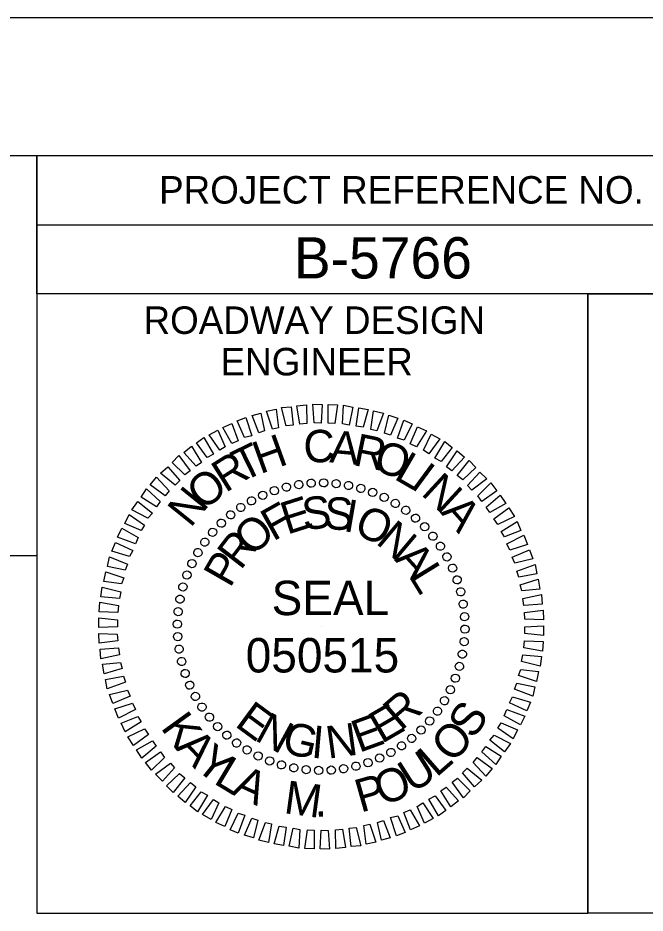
# Model space of a CAD drawing. Extents: x 573078 to 573143.6, y -55221.3 to -55199.3.
# Drawn here: x 573107.444 to 573109.723, y -55202.55 to -55199.298 of the extents above; entities that cross this region are included whole.
import ezdxf

# ---------------------------------------------------------------- set-up
doc = ezdxf.new("R2010")
doc.units = 0
for name, color, linetype in [('Prop Dimension', 7, 'Continuous'), ('Prop DSN Text', 7, 'Continuous'), ('Scratch_Level_1', 7, 'Continuous'), ('Sheet Plan CELL', 7, 'Continuous'), ('Sheet Plot Border Inside CELL', 7, 'Continuous')]:
    doc.layers.add(name, color=color, linetype=linetype)

msp = doc.modelspace()

# ---------------------------------------------------------------- linework, layer by layer
at = {"layer": 'Prop Dimension'}
for p, q in [((573108.4648, -55200.9939), (573108.4648, -55200.9939)), ((573108.5094, -55200.9876), (573108.5094, -55200.9876)), ((573108.5553, -55200.9867), (573108.5553, -55200.9867)), ((573108.6011, -55200.9897), (573108.6011, -55200.9897)), ((573108.646, -55200.9971), (573108.646, -55200.9971)), ((573108.3336, -55201.0314), (573108.3336, -55201.0314)), ((573108.3752, -55201.0147), (573108.3752, -55201.0147)), ((573108.419, -55201.0022), (573108.419, -55201.0022)), ((573108.6897, -55201.0064), (573108.6897, -55201.0064)), ((573108.7335, -55201.0209), (573108.7335, -55201.0209)), ((573108.2928, -55201.0522), (573108.2928, -55201.0522)), ((573108.7751, -55201.0397), (573108.7751, -55201.0397)), ((573108.8156, -55201.0605), (573108.8156, -55201.0605)), ((573108.2533, -55201.0762), (573108.2533, -55201.0762)), ((573108.8531, -55201.0867), (573108.8531, -55201.0867)), ((573108.2169, -55201.1022), (573108.2169, -55201.1022)), ((573108.8897, -55201.1147), (573108.8897, -55201.1147)), ((573108.1825, -55201.1334), (573108.1825, -55201.1334)), ((573108.9218, -55201.1459), (573108.9218, -55201.1459)), ((573108.1512, -55201.1658), (573108.1512, -55201.1658)), ((573108.9531, -55201.1804), (573108.9531, -55201.1804)), ((573108.1232, -55201.2021), (573108.1232, -55201.2021)), ((573108.9792, -55201.2167), (573108.9792, -55201.2167)), ((573108.0971, -55201.2396), (573108.0971, -55201.2396)), ((573109.0031, -55201.2563), (573109.0031, -55201.2563)), ((573108.0762, -55201.2804), (573108.0762, -55201.2804)), ((573108.0575, -55201.322), (573108.0575, -55201.322)), ((573109.0239, -55201.297), (573109.0239, -55201.297)), ((573109.0405, -55201.3387), (573109.0405, -55201.3387)), ((573108.0429, -55201.3658), (573108.0429, -55201.3658)), ((573109.053, -55201.3824), (573109.053, -55201.3824)), ((573108.0337, -55201.4095), (573108.0337, -55201.4095)), ((573108.0262, -55201.4542), (573108.0262, -55201.4542)), ((573109.0614, -55201.4282), (573109.0614, -55201.4282)), ((573109.0676, -55201.4729), (573109.0676, -55201.4729)), ((573108.0232, -55201.5), (573108.0232, -55201.5)), ((573108.546, -55201.5095), (573108.546, -55201.5095)), ((573109.0688, -55201.5187), (573109.0688, -55201.5187)), ((573108.0242, -55201.5458), (573108.0242, -55201.5458)), ((573109.0655, -55201.5645), (573109.0655, -55201.5645)), ((573108.0304, -55201.5907), (573108.0304, -55201.5907)), ((573109.0584, -55201.6094), (573109.0584, -55201.6094)), ((573108.0387, -55201.6365), (573108.0387, -55201.6365)), ((573108.0512, -55201.6802), (573108.0512, -55201.6802)), ((573109.0489, -55201.6532), (573109.0489, -55201.6532)), ((573109.0343, -55201.6969), (573109.0343, -55201.6969)), ((573108.0679, -55201.7219), (573108.0679, -55201.7219)), ((573109.0156, -55201.7386), (573109.0156, -55201.7386)), ((573108.0887, -55201.7624), (573108.0887, -55201.7624)), ((573108.9947, -55201.7791), (573108.9947, -55201.7791)), ((573108.1128, -55201.802), (573108.1128, -55201.802)), ((573108.1387, -55201.8385), (573108.1387, -55201.8385)), ((573108.9688, -55201.8166), (573108.9688, -55201.8166)), ((573108.17, -55201.8728), (573108.17, -55201.8728)), ((573108.9406, -55201.8531), (573108.9406, -55201.8531)), ((573108.2024, -55201.904), (573108.2024, -55201.904)), ((573108.9093, -55201.8853), (573108.9093, -55201.8853)), ((573108.2387, -55201.9323), (573108.2387, -55201.9323)), ((573108.8751, -55201.9165), (573108.8751, -55201.9165)), ((573108.2762, -55201.9582), (573108.2762, -55201.9582)), ((573108.7989, -55201.9665), (573108.7989, -55201.9665)), ((573108.8385, -55201.9427), (573108.8385, -55201.9427)), ((573108.3169, -55201.979), (573108.3169, -55201.979)), ((573108.3586, -55201.9977), (573108.3586, -55201.9977)), ((573108.7168, -55202.004), (573108.7168, -55202.004)), ((573108.7584, -55201.9873), (573108.7584, -55201.9873)), ((573108.4023, -55202.0123), (573108.4023, -55202.0123)), ((573108.446, -55202.0218), (573108.446, -55202.0218)), ((573108.4907, -55202.029), (573108.4907, -55202.029)), ((573108.5365, -55202.0322), (573108.5365, -55202.0322)), ((573108.5823, -55202.0311), (573108.5823, -55202.0311)), ((573108.6272, -55202.0248), (573108.6272, -55202.0248)), ((573108.6731, -55202.0165), (573108.6731, -55202.0165))]:
    msp.add_line(p, q, dxfattribs=at)
for points in [[(573108.4689, -55200.7742), (573108.4574, -55200.7076), (573108.4928, -55200.7034), (573108.4939, -55200.771)], [(573108.521, -55200.7689), (573108.5157, -55200.7014), (573108.5502, -55200.7023), (573108.546, -55200.7701)], [(573108.571, -55200.7701), (573108.571, -55200.7023), (573108.6053, -55200.7034), (573108.596, -55200.771)], [(573108.6231, -55200.7731), (573108.6272, -55200.7055), (573108.6615, -55200.7118), (573108.6481, -55200.7773)], [(573108.319, -55200.8055), (573108.2949, -55200.743), (573108.3273, -55200.7335), (573108.3407, -55200.7981)], [(573108.369, -55200.7918), (573108.347, -55200.7263), (573108.3824, -55200.7189), (573108.3907, -55200.7867)], [(573108.419, -55200.7805), (573108.4023, -55200.7138), (573108.4365, -55200.7106), (573108.444, -55200.7773)], [(573108.6731, -55200.7814), (573108.6823, -55200.7148), (573108.7168, -55200.7201), (573108.6981, -55200.7847)], [(573108.7261, -55200.793), (573108.7365, -55200.7252), (573108.7719, -55200.7335), (573108.748, -55200.7981)], [(573108.222, -55200.8439), (573108.1887, -55200.7856), (573108.2211, -55200.771), (573108.2449, -55200.8346)], [(573108.2678, -55200.8221), (573108.2408, -55200.7617), (573108.272, -55200.7493), (573108.294, -55200.8159)], [(573108.776, -55200.8064), (573108.7918, -55200.7418), (573108.8239, -55200.7523), (573108.798, -55200.8138)], [(573108.823, -55200.8252), (573108.8468, -55200.7597), (573108.876, -55200.7722), (573108.8469, -55200.8326)], [(573108.1774, -55200.8689), (573108.1387, -55200.8127), (573108.1711, -55200.796), (573108.197, -55200.8564)], [(573108.8698, -55200.8451), (573108.8959, -55200.7835), (573108.9281, -55200.7981), (573108.8927, -55200.8564)], [(573108.1315, -55200.895), (573108.0929, -55200.8418), (573108.12, -55200.8222), (573108.1544, -55200.8825)], [(573108.9177, -55200.8689), (573108.9459, -55200.8097), (573108.9771, -55200.8272), (573108.9376, -55200.8814)], [(573108.9584, -55200.8971), (573108.9947, -55200.8367), (573109.0218, -55200.8585), (573108.9813, -55200.9096)], [(573108.092, -55200.9263), (573108.0471, -55200.8763), (573108.0753, -55200.8543), (573108.1116, -55200.9126)], [(573108.0503, -55200.9585), (573108.0045, -55200.9126), (573108.0295, -55200.8876), (573108.07, -55200.9439)], [(573109.001, -55200.9284), (573109.0396, -55200.871), (573109.0667, -55200.8939), (573109.0209, -55200.943)], [(573108.0158, -55200.995), (573107.9628, -55200.9522), (573107.9888, -55200.9284), (573108.0325, -55200.9784)], [(573109.0405, -55200.9605), (573109.0834, -55200.9064), (573109.1084, -55200.9314), (573109.0604, -55200.9763)], [(573107.9795, -55201.0346), (573107.9253, -55200.9939), (573107.9483, -55200.9668), (573107.9941, -55201.0158)], [(573109.078, -55200.9971), (573109.1229, -55200.948), (573109.1479, -55200.973), (573109.0938, -55201.0138)], [(573109.1146, -55201.0346), (573109.1625, -55200.9876), (573109.1843, -55201.0158), (573109.1292, -55201.0554)], [(573107.9483, -55201.0742), (573107.892, -55201.0388), (573107.9117, -55201.0084), (573107.9617, -55201.0543)], [(573109.1458, -55201.0751), (573109.1968, -55201.0314), (573109.2167, -55201.0617), (573109.1583, -55201.095)], [(573107.917, -55201.1158), (573107.8587, -55201.0846), (573107.8795, -55201.0554), (573107.9337, -55201.0971)], [(573109.1729, -55201.1179), (573109.228, -55201.0783), (573109.2479, -55201.1096), (573109.1875, -55201.1387)], [(573107.892, -55201.1605), (573107.8325, -55201.1346), (573107.8483, -55201.1022), (573107.9045, -55201.1408)], [(573109.2, -55201.1637), (573109.2583, -55201.1272), (573109.2717, -55201.1596), (573109.2125, -55201.1834)], [(573107.8712, -55201.2084), (573107.8066, -55201.1846), (573107.8221, -55201.1522), (573107.8816, -55201.1855)], [(573109.2208, -55201.2084), (573109.2821, -55201.1771), (573109.2958, -55201.2105), (573109.2312, -55201.2313)], [(573107.8504, -55201.2542), (573107.7858, -55201.2355), (573107.7992, -55201.2033), (573107.8617, -55201.2325)], [(573107.8346, -55201.3042), (573107.7701, -55201.2908), (573107.7775, -55201.2563), (573107.843, -55201.2824)], [(573109.2396, -55201.2574), (573109.303, -55201.2304), (573109.3145, -55201.2625), (573109.25, -55201.2792)], [(573109.2562, -55201.3074), (573109.3229, -55201.2834), (573109.3291, -55201.3178), (573109.2634, -55201.3292)], [(573107.8212, -55201.3542), (573107.7566, -55201.3458), (573107.7638, -55201.3104), (573107.8295, -55201.3324)], [(573109.2687, -55201.3574), (573109.3342, -55201.3375), (573109.3405, -55201.3729), (573109.275, -55201.3792)], [(573107.8129, -55201.4074), (573107.7462, -55201.4012), (573107.7504, -55201.3658), (573107.818, -55201.3824)], [(573107.8076, -55201.4574), (573107.74, -55201.4553), (573107.7421, -55201.4208), (573107.8096, -55201.4324)], [(573109.278, -55201.4074), (573109.3458, -55201.3928), (573109.3488, -55201.4282), (573109.2821, -55201.4324)], [(573109.2842, -55201.4574), (573109.352, -55201.4491), (573109.3541, -55201.4845), (573109.2863, -55201.4824)], [(573107.8066, -55201.5095), (573107.7388, -55201.5125), (573107.7388, -55201.4771), (573107.8066, -55201.4845)], [(573109.2854, -55201.5095), (573109.353, -55201.5062), (573109.353, -55201.5416), (573109.2854, -55201.5345)], [(573107.8076, -55201.5615), (573107.74, -55201.5699), (573107.7379, -55201.5345), (573107.8055, -55201.5365)], [(573109.2842, -55201.5615), (573109.352, -55201.5636), (573109.35, -55201.5979), (573109.2821, -55201.5865)], [(573107.8138, -55201.6115), (573107.7462, -55201.6261), (573107.743, -55201.5907), (573107.8096, -55201.5865)], [(573109.2791, -55201.6115), (573109.3458, -55201.6178), (573109.3416, -55201.6532), (573109.2738, -55201.6365)], [(573107.8233, -55201.6615), (573107.7576, -55201.6812), (573107.7513, -55201.6458), (573107.817, -55201.6395)], [(573109.2708, -55201.6645), (573109.3354, -55201.6728), (573109.328, -55201.7082), (573109.2625, -55201.6865)], [(573107.8358, -55201.7115), (573107.7691, -55201.7353), (573107.7629, -55201.7011), (573107.8284, -55201.6895)], [(573109.2572, -55201.7145), (573109.3217, -55201.7281), (573109.3145, -55201.7624), (573109.2488, -55201.7365)], [(573107.8524, -55201.7615), (573107.7888, -55201.7885), (573107.7775, -55201.7562), (573107.842, -55201.7395)], [(573109.2416, -55201.7645), (573109.3062, -55201.7832), (573109.2926, -55201.8156), (573109.2301, -55201.7865)], [(573107.8712, -55201.8103), (573107.8096, -55201.8415), (573107.7962, -55201.8082), (573107.8608, -55201.7874)], [(573109.2208, -55201.8103), (573109.2854, -55201.8344), (573109.2696, -55201.8665), (573109.2104, -55201.8332)], [(573107.892, -55201.8552), (573107.8337, -55201.8915), (573107.8201, -55201.8594), (573107.8795, -55201.8353)], [(573109.2, -55201.8582), (573109.2592, -55201.8844), (573109.2437, -55201.9165), (573109.1875, -55201.8781)], [(573107.9191, -55201.901), (573107.8638, -55201.9406), (573107.8441, -55201.9093), (573107.9045, -55201.8802)], [(573109.175, -55201.9031), (573109.2333, -55201.9343), (573109.2125, -55201.9635), (573109.1583, -55201.9218)], [(573107.9462, -55201.9436), (573107.895, -55201.9873), (573107.8754, -55201.9573), (573107.9337, -55201.9239)], [(573107.9774, -55201.9843), (573107.9295, -55202.0311), (573107.9075, -55202.0031), (573107.9628, -55201.9635)], [(573109.1438, -55201.9448), (573109.2, -55201.9802), (573109.1801, -55202.0102), (573109.1301, -55201.9644)], [(573108.0137, -55202.0218), (573107.9691, -55202.0706), (573107.9441, -55202.0457), (573107.9982, -55202.0052)], [(573109.1125, -55201.9843), (573109.1667, -55202.0248), (573109.1438, -55202.0519), (573109.0979, -55202.0031)], [(573109.076, -55202.0239), (573109.1292, -55202.0665), (573109.103, -55202.0906), (573109.0593, -55202.0406)], [(573108.0512, -55202.0581), (573108.0087, -55202.1123), (573107.9837, -55202.0873), (573108.0316, -55202.0426)], [(573109.0417, -55202.0602), (573109.0875, -55202.1061), (573109.0625, -55202.131), (573109.0218, -55202.0748)], [(573108.0908, -55202.0906), (573108.0524, -55202.1477), (573108.0253, -55202.1248), (573108.0711, -55202.076)], [(573109.0001, -55202.0926), (573109.0447, -55202.1426), (573109.0167, -55202.1644), (573108.9801, -55202.1061)], [(573108.1336, -55202.1218), (573108.0971, -55202.1822), (573108.07, -55202.1602), (573108.1107, -55202.1093)], [(573108.1741, -55202.1498), (573108.1461, -55202.2093), (573108.1149, -55202.1914), (573108.1544, -55202.1373)], [(573108.9605, -55202.1239), (573108.9989, -55202.1769), (573108.9718, -55202.1968), (573108.9376, -55202.1364)], [(573108.222, -55202.1739), (573108.1961, -55202.2352), (573108.1637, -55202.2206), (573108.1991, -55202.1623)], [(573108.9147, -55202.1498), (573108.9531, -55202.206), (573108.9209, -55202.2227), (573108.8948, -55202.1623)], [(573108.269, -55202.1935), (573108.2449, -55202.2592), (573108.2158, -55202.2468), (573108.2449, -55202.1864)], [(573108.8239, -55202.1968), (573108.851, -55202.2572), (573108.8198, -55202.2697), (573108.798, -55202.203)], [(573108.8698, -55202.1748), (573108.9031, -55202.2331), (573108.8709, -55202.2477), (573108.8468, -55202.1843)], [(573108.3158, -55202.2123), (573108.3002, -55202.2768), (573108.2678, -55202.2664), (573108.294, -55202.2051)], [(573108.3657, -55202.2259), (573108.3553, -55202.2935), (573108.3199, -55202.2852), (573108.344, -55202.2206)], [(573108.419, -55202.2373), (573108.4095, -55202.3039), (573108.3752, -55202.2988), (573108.394, -55202.2343)], [(573108.723, -55202.2269), (573108.7448, -55202.2926), (573108.7094, -55202.2997), (573108.7011, -55202.2322)], [(573108.773, -55202.2134), (573108.7969, -55202.2759), (573108.7647, -55202.2852), (573108.751, -55202.2206)], [(573108.4689, -55202.2456), (573108.4648, -55202.3134), (573108.4303, -55202.3072), (573108.444, -55202.2414)], [(573108.521, -55202.2488), (573108.521, -55202.3164), (573108.4865, -55202.3155), (573108.496, -55202.2477)], [(573108.571, -55202.2498), (573108.5761, -55202.3176), (573108.5418, -55202.3164), (573108.546, -55202.2488)], [(573108.6231, -55202.2447), (573108.6344, -55202.3113), (573108.599, -55202.3155), (573108.5981, -55202.2477)], [(573108.6731, -55202.2384), (573108.6897, -55202.3051), (573108.6552, -55202.3081), (573108.6481, -55202.2414)]]:
    msp.add_lwpolyline(points, close=True, dxfattribs=at)
for centre, major_axis in [((573108.376, -55201.0155), (-0.0049, 0.0142)), ((573108.4196, -55201.0026), (-0.0036, 0.0146)), ((573108.4643, -55200.9935), (-0.0023, 0.0148)), ((573108.5096, -55200.9883), (-0.001, 0.015)), ((573108.5551, -55200.9871), (0.0003, 0.015)), ((573108.6006, -55200.9899), (0.0016, 0.0149)), ((573108.6457, -55200.9966), (0.0029, 0.0147)), ((573108.69, -55201.0073), (0.0041, 0.0144)), ((573108.3336, -55201.0322), (-0.0061, 0.0137)), ((573108.7332, -55201.0217), (0.0054, 0.014)), ((573108.775, -55201.0399), (0.0066, 0.0135)), ((573108.2539, -55201.0763), (-0.0084, 0.0124)), ((573108.2928, -55201.0525), (-0.0073, 0.0131)), ((573108.8151, -55201.0616), (0.0077, 0.0129)), ((573108.2173, -55201.1034), (-0.0094, 0.0117)), ((573108.8531, -55201.0868), (0.0088, 0.0121)), ((573108.1832, -55201.1336), (-0.0104, 0.0108)), ((573108.8887, -55201.1152), (0.0098, 0.0113)), ((573108.1518, -55201.1667), (-0.0113, 0.0098)), ((573108.9218, -55201.1465), (0.0108, 0.0104)), ((573108.1234, -55201.2024), (-0.0121, 0.0088)), ((573108.952, -55201.1807), (0.0117, 0.0094)), ((573108.0983, -55201.2404), (-0.0129, 0.0077)), ((573108.9791, -55201.2173), (0.0124, 0.0084)), ((573109.0029, -55201.2562), (0.0131, 0.0073)), ((573108.0765, -55201.2804), (-0.0135, 0.0066)), ((573109.0232, -55201.2969), (0.0137, 0.0061)), ((573108.0584, -55201.3222), (-0.014, 0.0054)), ((573109.0399, -55201.3393), (0.0142, 0.0049)), ((573108.0439, -55201.3654), (-0.0144, 0.0041)), ((573109.0529, -55201.383), (0.0146, 0.0036)), ((573108.0333, -55201.4097), (-0.0147, 0.0029)), ((573109.0619, -55201.4277), (0.0148, 0.0023)), ((573108.0265, -55201.4548), (-0.0149, 0.0016)), ((573108.0237, -55201.5003), (-0.015, 0.0003)), ((573109.0671, -55201.473), (0.015, 0.001)), ((573109.0683, -55201.5185), (0.015, -0.0003)), ((573108.0249, -55201.5458), (-0.015, -0.001)), ((573109.0655, -55201.564), (0.0149, -0.0016)), ((573108.0301, -55201.5911), (-0.0148, -0.0023)), ((573109.0588, -55201.6091), (0.0147, -0.0029)), ((573108.0392, -55201.6358), (-0.0146, -0.0036)), ((573109.0481, -55201.6534), (0.0144, -0.0041)), ((573108.0521, -55201.6795), (-0.0142, -0.0049)), ((573109.0337, -55201.6966), (0.014, -0.0054)), ((573108.0688, -55201.7219), (-0.0137, -0.0061)), ((573108.0892, -55201.7626), (-0.0131, -0.0073)), ((573109.0155, -55201.7384), (0.0135, -0.0066)), ((573108.9938, -55201.7784), (0.0129, -0.0077)), ((573108.113, -55201.8015), (-0.0124, -0.0084)), ((573108.9686, -55201.8164), (0.0121, -0.0088)), ((573108.1401, -55201.8381), (-0.0117, -0.0094)), ((573108.9402, -55201.8521), (0.0113, -0.0098)), ((573108.1703, -55201.8723), (-0.0108, -0.0104)), ((573108.9089, -55201.8851), (0.0104, -0.0108)), ((573108.2033, -55201.9036), (-0.0098, -0.0113)), ((573108.8747, -55201.9153), (0.0094, -0.0117)), ((573108.239, -55201.932), (-0.0088, -0.0121)), ((573108.277, -55201.9571), (-0.0077, -0.0129)), ((573108.8381, -55201.9424), (0.0084, -0.0124)), ((573108.317, -55201.9789), (-0.0066, -0.0135)), ((573108.7585, -55201.9866), (0.0061, -0.0137)), ((573108.7993, -55201.9663), (0.0073, -0.0131)), ((573108.3588, -55201.9971), (-0.0054, -0.014)), ((573108.402, -55202.0115), (-0.0041, -0.0144)), ((573108.4463, -55202.0222), (-0.0029, -0.0147)), ((573108.6724, -55202.0162), (0.0036, -0.0146)), ((573108.7161, -55202.0033), (0.0049, -0.0142)), ((573108.4914, -55202.0289), (-0.0016, -0.0149)), ((573108.5369, -55202.0317), (-0.0003, -0.015)), ((573108.5825, -55202.0305), (0.001, -0.015)), ((573108.6277, -55202.0253), (0.0023, -0.0148))]:
    msp.add_ellipse(centre, major_axis=major_axis, ratio=0.999708, dxfattribs=at)
at = {"layer": 'Scratch_Level_1'}
msp.add_line((573108.546, -55201.5095), (573108.546, -55201.5095), dxfattribs=at)
at = {"layer": 'Sheet Plan CELL'}
for p, q in [((573107.5132, -55200.0494), (573111.5142, -55200.0497)), ((573109.5142, -55200.3002), (573109.5144, -55202.5494))]:
    msp.add_line(p, q, dxfattribs=at)
for points in [[(573081.5142, -55199.7984), (573111.5142, -55199.7984), (573111.5142, -55220.7984), (573081.5142, -55220.7984)], [(573107.5132, -55201.252), (573104.5124, -55201.252), (573104.5124, -55199.7984), (573107.5132, -55199.7984)], [(573107.5132, -55199.7984), (573111.5142, -55199.7984), (573111.5142, -55200.3002), (573107.5132, -55200.3002)], [(573109.5142, -55200.3002), (573107.5132, -55200.3002), (573107.5132, -55202.5502), (573109.5142, -55202.5502)], [(573109.5142, -55200.3002), (573111.5142, -55200.3002), (573111.5142, -55202.5502), (573109.5142, -55202.5502)]]:
    msp.add_lwpolyline(points, close=True, dxfattribs=at)
at = {"layer": 'Sheet Plot Border Inside CELL'}
msp.add_lwpolyline([(573112.0142, -55199.2984), (573078.0142, -55199.2984), (573078.0142, -55221.2984), (573112.0142, -55221.2984)], close=True, dxfattribs=at)

# ---------------------------------------------------------------- texts
at = {"layer": 'Prop Dimension'}
for s, height, rotation, p in [('C', 0.1177, 1.0718, (573108.4826, -55200.9136)), ('A', 0.1177, 354.8222, (573108.5742, -55200.9124)), ('H', 0.1177, 19.8207, (573108.3243, -55200.9561)), ('R', 0.1177, 348.5725, (573108.6576, -55200.9219)), ('T', 0.1177, 26.0703, (573108.2609, -55200.9853)), ('O', 0.1177, 342.3229, (573108.7304, -55200.9406)), ('R', 0.1177, 32.3199, (573108.1984, -55201.0249)), ('L', 0.1177, 329.8237, (573108.8066, -55200.9707)), ('I', 0.1177, 323.5741, (573108.8649, -55201.001)), ('O', 0.1177, 38.5695, (573108.1181, -55201.0906)), ('N', 0.1177, 317.3244, (573108.9054, -55201.0281)), ('N', 0.1177, 51.0688, (573108.0714, -55201.1531)), ('F', 0.1177, 29.3, (573108.3713, -55201.201)), ('E', 0.1177, 17.6709, (573108.4222, -55201.176)), ('S', 0.1177, 6.1833, (573108.4826, -55201.1593)), ('S', 0.1177, 358.4778, (573108.5567, -55201.1561)), ('I', 0.1177, 350.0931, (573108.6233, -55201.1614)), ('A', 0.1177, 311.0748, (573108.9774, -55201.0957)), ('O', 0.1177, 335.3611, (573108.6596, -55201.1686)), ('O', 0.1177, 43.5875, (573108.2972, -55201.2572)), ('N', 0.1177, 319.95, (573108.7409, -55201.2051)), ('R', 0.1177, 52.4166, (573108.2535, -55201.3072)), ('A', 0.1177, 312.2445, (573108.8096, -55201.2665)), ('P', 0.1177, 60.1222, (573108.2151, -55201.3718)), ('L', 0.1177, 301.6752, (573108.8617, -55201.3248)), ('SEAL', 0.12497, 360, (573108.366, -55201.4676)), ('050515', 0.12497, 360, (573108.2719, -55201.6758)), ('R', 0.1177, 40.7353, (573108.8357, -55201.8904)), ('E', 0.1177, 323.6798, (573108.2285, -55201.8684)), ('E', 0.1177, 30.1214, (573108.7659, -55201.9362)), ('S', 0.12, 57.1863, (573109.1004, -55201.9217)), ('K', 0.12, 305.9043, (573107.9606, -55201.8764)), ('N', 0.1177, 331.3854, (573108.3005, -55201.9195)), ('E', 0.1177, 20.0411, (573108.6837, -55201.9684)), ('G', 0.1177, 346.7965, (573108.3993, -55201.9654)), ('I', 0.1177, 355.0405, (573108.5076, -55201.985)), ('N', 0.1177, 7.7341, (573108.5712, -55201.9892)), ('O', 0.12, 47.4888, (573109.0231, -55202.0092)), ('A', 0.12, 313.5599, (573108.0147, -55201.9511)), ('Y', 0.12, 321.5623, (573108.0814, -55202.0208)), ('U', 0.12, 32.399, (573108.8765, -55202.1162)), ('L', 0.12, 41.0852, (573108.9643, -55202.0593)), ('L', 0.12, 328.9868, (573108.1513, -55202.0766)), ('A', 0.12, 335.3904, (573108.2171, -55202.117)), ('O', 0.12, 22.7015, (573108.7696, -55202.1632)), ('M', 0.12, 352.2427, (573108.4073, -55202.1863)), ('P', 0.12, 15.7778, (573108.6891, -55202.1854)), ('.', 0.12, 1.9209, (573108.5231, -55202.2))]:
    msp.add_text(s, height=height, rotation=rotation, dxfattribs=at).set_placement(p)
at = {"layer": 'Prop DSN Text'}
msp.add_text('B-5766', height=0.15, rotation=0, dxfattribs=at).set_placement((573108.4467, -55200.2449))
at = {"layer": 'Sheet Plan CELL'}
for s, height, p in [('PROJECT REFERENCE NO.', 0.100002, (573107.9572, -55199.9729)), ('ROADWAY DESIGN', 0.100002, (573107.9007, -55200.4462)), ('ENGINEER', 0.1, (573108.1804, -55200.5969))]:
    msp.add_text(s, height=height, rotation=0, dxfattribs=at).set_placement(p)

doc.saveas('drawing.dxf')
